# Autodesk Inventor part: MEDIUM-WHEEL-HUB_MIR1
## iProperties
Created: 2007-08
Part Number: MEDIUM-WHEEL-HUB_MIR1
Material: ABS Plastic
Document SubType Name: Modeling
Mass: 42.8255 g
Surface Area: 324.402 cm^2
Volume: 40.4014 cm^3
Density: 1.06 g/cm^3
